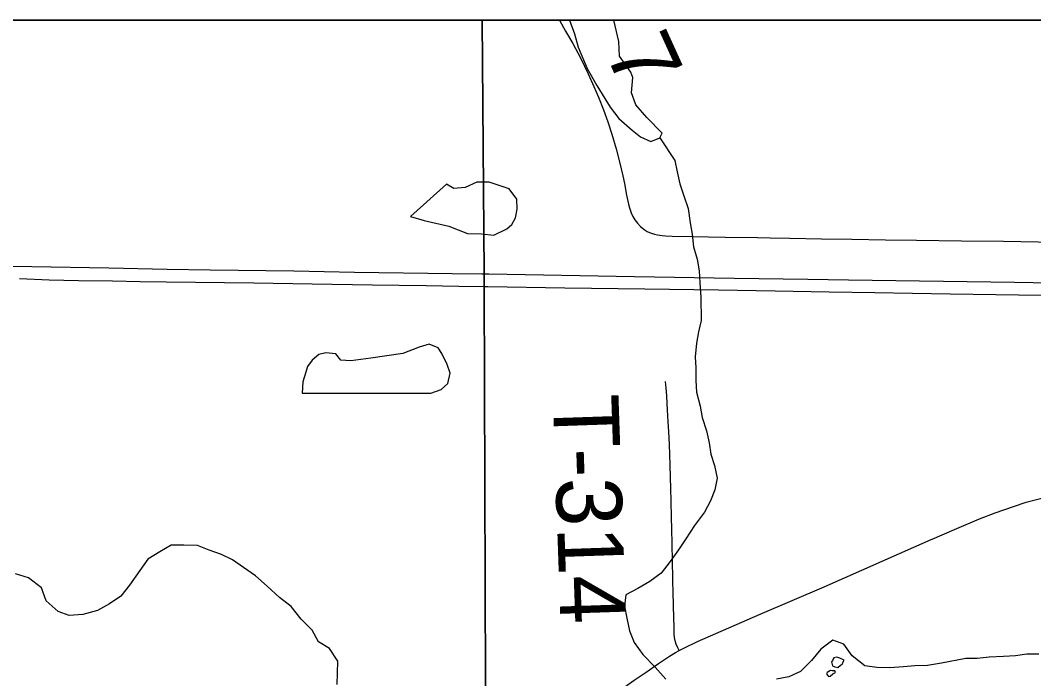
# Model space of a CAD drawing. Extents: x 0 to 34, y 0 to 22.
# Drawn here: x 4.634 to 5.511, y 20.048 to 20.617 of the extents above; entities that cross this region are included whole.
import ezdxf

# ---------------------------------------------------------------- set-up
doc = ezdxf.new("R2010")
doc.units = 0
for name, color, linetype in [('GM_X_Corporation', 7, 'Continuous'), ('GM_X_County_Road', 7, 'Continuous'), ('GM_X_Interstate_Route', 7, 'Continuous'), ('GM_X_Major_River', 7, 'Continuous'), ('GM_X_Minor_Lake', 7, 'Continuous'), ('GM_X_Minor_River', 7, 'Continuous'), ('GM_X_State_Route', 7, 'Continuous'), ('GM_X_Township_Road', 7, 'Continuous'), ('GM_X_Township_Road_Text', 7, 'Continuous'), ('SH_Data', 7, 'Continuous')]:
    doc.layers.add(name, color=color, linetype=linetype)

msp = doc.modelspace()

# ---------------------------------------------------------------- linework, layer by layer
at = {"layer": 'GM_X_Corporation'}
for points in [[(5.037, 19.96155), (5.03541, 20.38763), (5.03541, 20.39859), (5.03383, 20.61727), (2.11404, 20.61727)], [(5.03701, 19.95856), (5.03541, 20.38763), (5.03541, 20.39859), (5.03383, 20.61727), (2.11404, 20.61727)], [(8.91404, 20.61727), (5.03383, 20.61727), (5.03541, 20.39859), (5.03541, 20.38763), (5.03701, 19.95856)]]:
    msp.add_lwpolyline(points, dxfattribs=at)
at = {"layer": 'GM_X_County_Road'}
for points in [[(5.42299, 20.16886), (5.44208, 20.17722), (5.46391, 20.18632), (5.47729, 20.19141), (5.49312, 20.19712), (5.50413, 20.20062), (5.51302, 20.20297), (5.52363, 20.20555), (5.53066, 20.2069), (5.53415, 20.2074)], [(5.20416, 20.07242), (5.20815, 20.07458), (5.21997, 20.08021), (5.27406, 20.10398), (5.32944, 20.12769), (5.37951, 20.14973), (5.42208, 20.16846), (5.42299, 20.16886)], [(5.03641, 19.95747), (5.03722, 19.958), (5.06951, 19.97999), (5.10031, 20.00105), (5.11964, 20.01458), (5.14046, 20.02928), (5.14603, 20.03323), (5.1521, 20.03756), (5.15714, 20.04119), (5.16532, 20.04683), (5.17552, 20.05393), (5.18625, 20.06136), (5.19565, 20.0675), (5.20101, 20.07071), (5.20416, 20.07242)]]:
    msp.add_lwpolyline(points, dxfattribs=at)
at = {"layer": 'GM_X_Interstate_Route'}
for points in [[(4.62757, 20.40461), (4.64426, 20.40434), (4.71097, 20.40323), (4.76127, 20.40228), (4.79853, 20.40158), (4.87076, 20.4006), (4.92322, 20.39963), (5.00768, 20.39843), (5.03337, 20.39806), (5.03562, 20.39803), (5.03961, 20.39797)], [(4.6338, 20.39406), (4.65935, 20.39304), (4.68473, 20.39245), (4.71398, 20.39194), (4.73802, 20.39161), (4.76037, 20.39131), (4.83635, 20.39027), (4.88678, 20.38948), (4.93906, 20.38867), (4.98544, 20.38794), (5.01369, 20.3875), (5.03562, 20.38708), (5.03864, 20.38703)], [(5.03961, 20.39797), (5.16554, 20.39586), (5.25162, 20.39445), (5.31535, 20.3934), (5.35054, 20.39289), (5.49414, 20.39078), (5.54281, 20.39), (5.56072, 20.38971), (5.59485, 20.38916), (5.69749, 20.38762), (5.73299, 20.38709), (5.78889, 20.38624), (5.81921, 20.38579), (5.84922, 20.38529), (5.90735, 20.38434), (5.96739, 20.38335), (5.99461, 20.38298), (6.061, 20.38194), (6.12711, 20.3809), (6.18106, 20.37968)], [(5.03864, 20.38703), (5.10513, 20.38604), (5.17438, 20.38507), (5.23809, 20.3842), (5.287, 20.38331), (5.3339, 20.38247), (5.37339, 20.38185), (5.43846, 20.38083), (5.47779, 20.38021), (5.51712, 20.37957), (5.55721, 20.37904), (5.56738, 20.37891), (5.67883, 20.37743), (5.78355, 20.37519), (5.81985, 20.37478), (5.8681, 20.37422), (5.9044, 20.37379), (5.99988, 20.37213), (6.04375, 20.37138), (6.10225, 20.37051), (6.14427, 20.36981)]]:
    msp.add_lwpolyline(points, dxfattribs=at)
at = {"layer": 'GM_X_Major_River'}
for p, q in [((5.34121, 20.05793), (5.34358, 20.05983)), ((5.33465, 20.05038), (5.33691, 20.05229))]:
    msp.add_line(p, q, dxfattribs=at)
for points in [[(5.51523, 20.0695), (5.50463, 20.06942), (5.4948, 20.06783), (5.48458, 20.06737), (5.4721, 20.0669), (5.46189, 20.06568), (5.45205, 20.0656), (5.43089, 20.06165), (5.41879, 20.05966), (5.40782, 20.05919), (5.39798, 20.05836), (5.38588, 20.05751), (5.3749, 20.05781), (5.36467, 20.05924), (5.35363, 20.06788), (5.34636, 20.07807), (5.33687, 20.08141), (5.32671, 20.07374), (5.31846, 20.06382), (5.30907, 20.05426), (5.29889, 20.04963), (5.2883, 20.04766)], [(5.34358, 20.05983), (5.34536, 20.06072), (5.34572, 20.06213), (5.34684, 20.06404), (5.34305, 20.0659), (5.34039, 20.06664), (5.33774, 20.06624), (5.337, 20.06472), (5.33663, 20.0632), (5.33588, 20.06282), (5.33666, 20.05941), (5.33856, 20.05828), (5.34121, 20.05793)], [(5.33691, 20.05229), (5.33917, 20.05344), (5.33878, 20.05496), (5.33651, 20.05494), (5.3349, 20.05538), (5.33198, 20.05339), (5.33161, 20.05225), (5.33314, 20.04998), (5.33465, 20.05038)]]:
    msp.add_lwpolyline(points, dxfattribs=at)
at = {"layer": 'GM_X_Minor_Lake'}
for p, q in [((5.00305, 20.47559), (4.97185, 20.44766)), ((4.87803, 20.29483), (4.9893, 20.29493))]:
    msp.add_line(p, q, dxfattribs=at)
for points in [[(5.10934, 20.61727), (5.11369, 20.60547), (5.11678, 20.5941), (5.12445, 20.57554), (5.13286, 20.56079), (5.14432, 20.54225), (5.15194, 20.53243), (5.16336, 20.52224), (5.17059, 20.51658), (5.17971, 20.51246), (5.18727, 20.51553), (5.18953, 20.51972), (5.1762, 20.53331), (5.16667, 20.54426), (5.16283, 20.55449), (5.1639, 20.56778), (5.16237, 20.57232), (5.15245, 20.58631), (5.15201, 20.59883), (5.14769, 20.61727)], [(4.97185, 20.44766), (4.98361, 20.44434), (5.00484, 20.43919), (5.02116, 20.43287), (5.03328, 20.43259), (5.04388, 20.43153), (5.05519, 20.43693), (5.05933, 20.44075), (5.06269, 20.44647), (5.06415, 20.45407), (5.0637, 20.46279), (5.0572, 20.47146), (5.03974, 20.47739), (5.02915, 20.47731), (5.01896, 20.47268), (5.00913, 20.47185), (5.00305, 20.47559)], [(4.9893, 20.29493), (4.99836, 20.29804), (5.00399, 20.3034), (5.0062, 20.31214), (5.00349, 20.3197), (4.99887, 20.32915), (4.99581, 20.33406), (4.98783, 20.33741), (4.97915, 20.33468), (4.96519, 20.32927), (4.93759, 20.32526), (4.9202, 20.32285), (4.91149, 20.32354), (4.90729, 20.32882), (4.89858, 20.32989), (4.89253, 20.32832), (4.88689, 20.32335), (4.88277, 20.31801), (4.8813, 20.31306), (4.87871, 20.3047), (4.87803, 20.29483)]]:
    msp.add_lwpolyline(points, dxfattribs=at)
at = {"layer": 'GM_X_Minor_River'}
for points in [[(5.18727, 20.51553), (5.20045, 20.49608), (5.20242, 20.48623), (5.20477, 20.47601), (5.20826, 20.46542), (5.21175, 20.45444), (5.21373, 20.44232), (5.21532, 20.43247), (5.21654, 20.42148), (5.21965, 20.41089), (5.22125, 20.40066), (5.22208, 20.39042), (5.22294, 20.37791), (5.22309, 20.35781), (5.22089, 20.34793), (5.21908, 20.33805), (5.21803, 20.32629), (5.21848, 20.31681), (5.21857, 20.30581), (5.21902, 20.29595), (5.22215, 20.28384), (5.22411, 20.27399), (5.22761, 20.26226), (5.22996, 20.25204), (5.23155, 20.24218), (5.23465, 20.23235), (5.23701, 20.22136), (5.23481, 20.21149), (5.2311, 20.20197), (5.22588, 20.19207), (5.21726, 20.18063), (5.20978, 20.16919), (5.20342, 20.15966), (5.19631, 20.14936), (5.18844, 20.13944), (5.17865, 20.13216), (5.16848, 20.12601), (5.15793, 20.12062), (5.15687, 20.11075), (5.15884, 20.10052), (5.16119, 20.08954), (5.16506, 20.07933), (5.1727, 20.06915), (5.18339, 20.05823), (5.19255, 20.04768)], [(4.90835, 20.04321), (4.90865, 20.05307), (4.90895, 20.06332), (4.90168, 20.07426), (4.89218, 20.07988), (4.8868, 20.09007), (4.87726, 20.09948), (4.86847, 20.11042), (4.85858, 20.1183), (4.8479, 20.12808), (4.83761, 20.13711), (4.82734, 20.14423), (4.81783, 20.15099), (4.80833, 20.15546), (4.7977, 20.15918), (4.78746, 20.16327), (4.77572, 20.16356), (4.76475, 20.16347), (4.75495, 20.1577), (4.74478, 20.15156), (4.73766, 20.14164), (4.72868, 20.12905), (4.72119, 20.11951), (4.7114, 20.11298), (4.70122, 20.10722), (4.68838, 20.1037), (4.67665, 20.10285), (4.66717, 20.10619), (4.65688, 20.11559), (4.65263, 20.12656), (4.64159, 20.1352), (4.63021, 20.1389)]]:
    msp.add_lwpolyline(points, dxfattribs=at)
at = {"layer": 'GM_X_State_Route'}
for points in [[(5.42299, 20.16886), (5.44208, 20.17722), (5.46391, 20.18632), (5.47729, 20.19141), (5.49312, 20.19712), (5.50413, 20.20062), (5.51302, 20.20297), (5.52363, 20.20555), (5.53066, 20.2069), (5.53415, 20.2074)], [(5.20416, 20.07242), (5.20815, 20.07458), (5.21997, 20.08021), (5.27406, 20.10398), (5.32944, 20.12769), (5.37951, 20.14973), (5.42208, 20.16846), (5.42299, 20.16886)], [(5.03641, 19.95747), (5.03722, 19.958), (5.06951, 19.97999), (5.10031, 20.00105), (5.11964, 20.01458), (5.14046, 20.02928), (5.14603, 20.03323), (5.1521, 20.03756), (5.15714, 20.04119), (5.16532, 20.04683), (5.17552, 20.05393), (5.18625, 20.06136), (5.19565, 20.0675), (5.20101, 20.07071), (5.20416, 20.07242)]]:
    msp.add_lwpolyline(points, dxfattribs=at)
at = {"layer": 'GM_X_Township_Road'}
for points in [[(5.10061, 20.61727), (5.10592, 20.60799), (5.11209, 20.5972), (5.11867, 20.58485), (5.12534, 20.57107), (5.13037, 20.56006), (5.13428, 20.55081), (5.1386, 20.53981), (5.14239, 20.52942), (5.14598, 20.51872), (5.14958, 20.50617), (5.15286, 20.49386), (5.15538, 20.48291), (5.15676, 20.47625), (5.15861, 20.46617), (5.16036, 20.45846), (5.16118, 20.45517), (5.16251, 20.45095), (5.16415, 20.44756), (5.16586, 20.44477), (5.16805, 20.442), (5.17064, 20.43906), (5.17381, 20.43645), (5.1765, 20.43474), (5.17989, 20.43327), (5.1829, 20.43226), (5.18528, 20.43172), (5.18726, 20.43141), (5.18944, 20.43113), (5.19236, 20.43098), (5.19817, 20.43079), (5.21513, 20.43047), (5.24384, 20.42994), (5.27171, 20.42943), (5.28279, 20.42922)], [(5.28279, 20.42922), (5.29992, 20.4289), (5.32731, 20.42846), (5.35351, 20.42805), (5.38256, 20.4276), (5.40935, 20.4272), (5.44812, 20.42664), (5.48464, 20.42621), (5.51439, 20.42587), (5.54723, 20.42545), (5.5547, 20.42536), (5.55909, 20.42512), (5.56336, 20.42453), (5.56691, 20.42393), (5.5718, 20.42268)], [(5.20416, 20.07242), (5.20298, 20.07495), (5.20152, 20.07805), (5.20069, 20.08079), (5.20015, 20.0838), (5.19988, 20.0869), (5.19969, 20.09046), (5.1997, 20.09475), (5.19961, 20.09894), (5.19949, 20.10332), (5.1993, 20.10889), (5.19912, 20.11418), (5.19889, 20.12039), (5.19862, 20.13471), (5.19833, 20.14976), (5.198, 20.16463), (5.19771, 20.1774), (5.19748, 20.18735), (5.19712, 20.20176), (5.19684, 20.21234), (5.19626, 20.2326), (5.19597, 20.24182), (5.1956, 20.25048), (5.19514, 20.26143), (5.19472, 20.27029), (5.19413, 20.28068), (5.1938, 20.28616), (5.19333, 20.29254), (5.19283, 20.29919), (5.19232, 20.30513)]]:
    msp.add_lwpolyline(points, dxfattribs=at)
at = {"layer": 'SH_Data'}
msp.add_line((2.11404, 20.61727), (8.91404, 20.61727), dxfattribs=at)

# ---------------------------------------------------------------- texts
at = {"layer": 'GM_X_Township_Road_Text'}
for s, height, rotation, p in [('7', 0.05682, 294.42496, (5.1394, 20.5901)), ('T-314', 0.056818, 271.94348, (5.09477, 20.29301))]:
    msp.add_text(s, height=height, rotation=rotation, dxfattribs=at).set_placement(p)

doc.saveas('drawing.dxf')
